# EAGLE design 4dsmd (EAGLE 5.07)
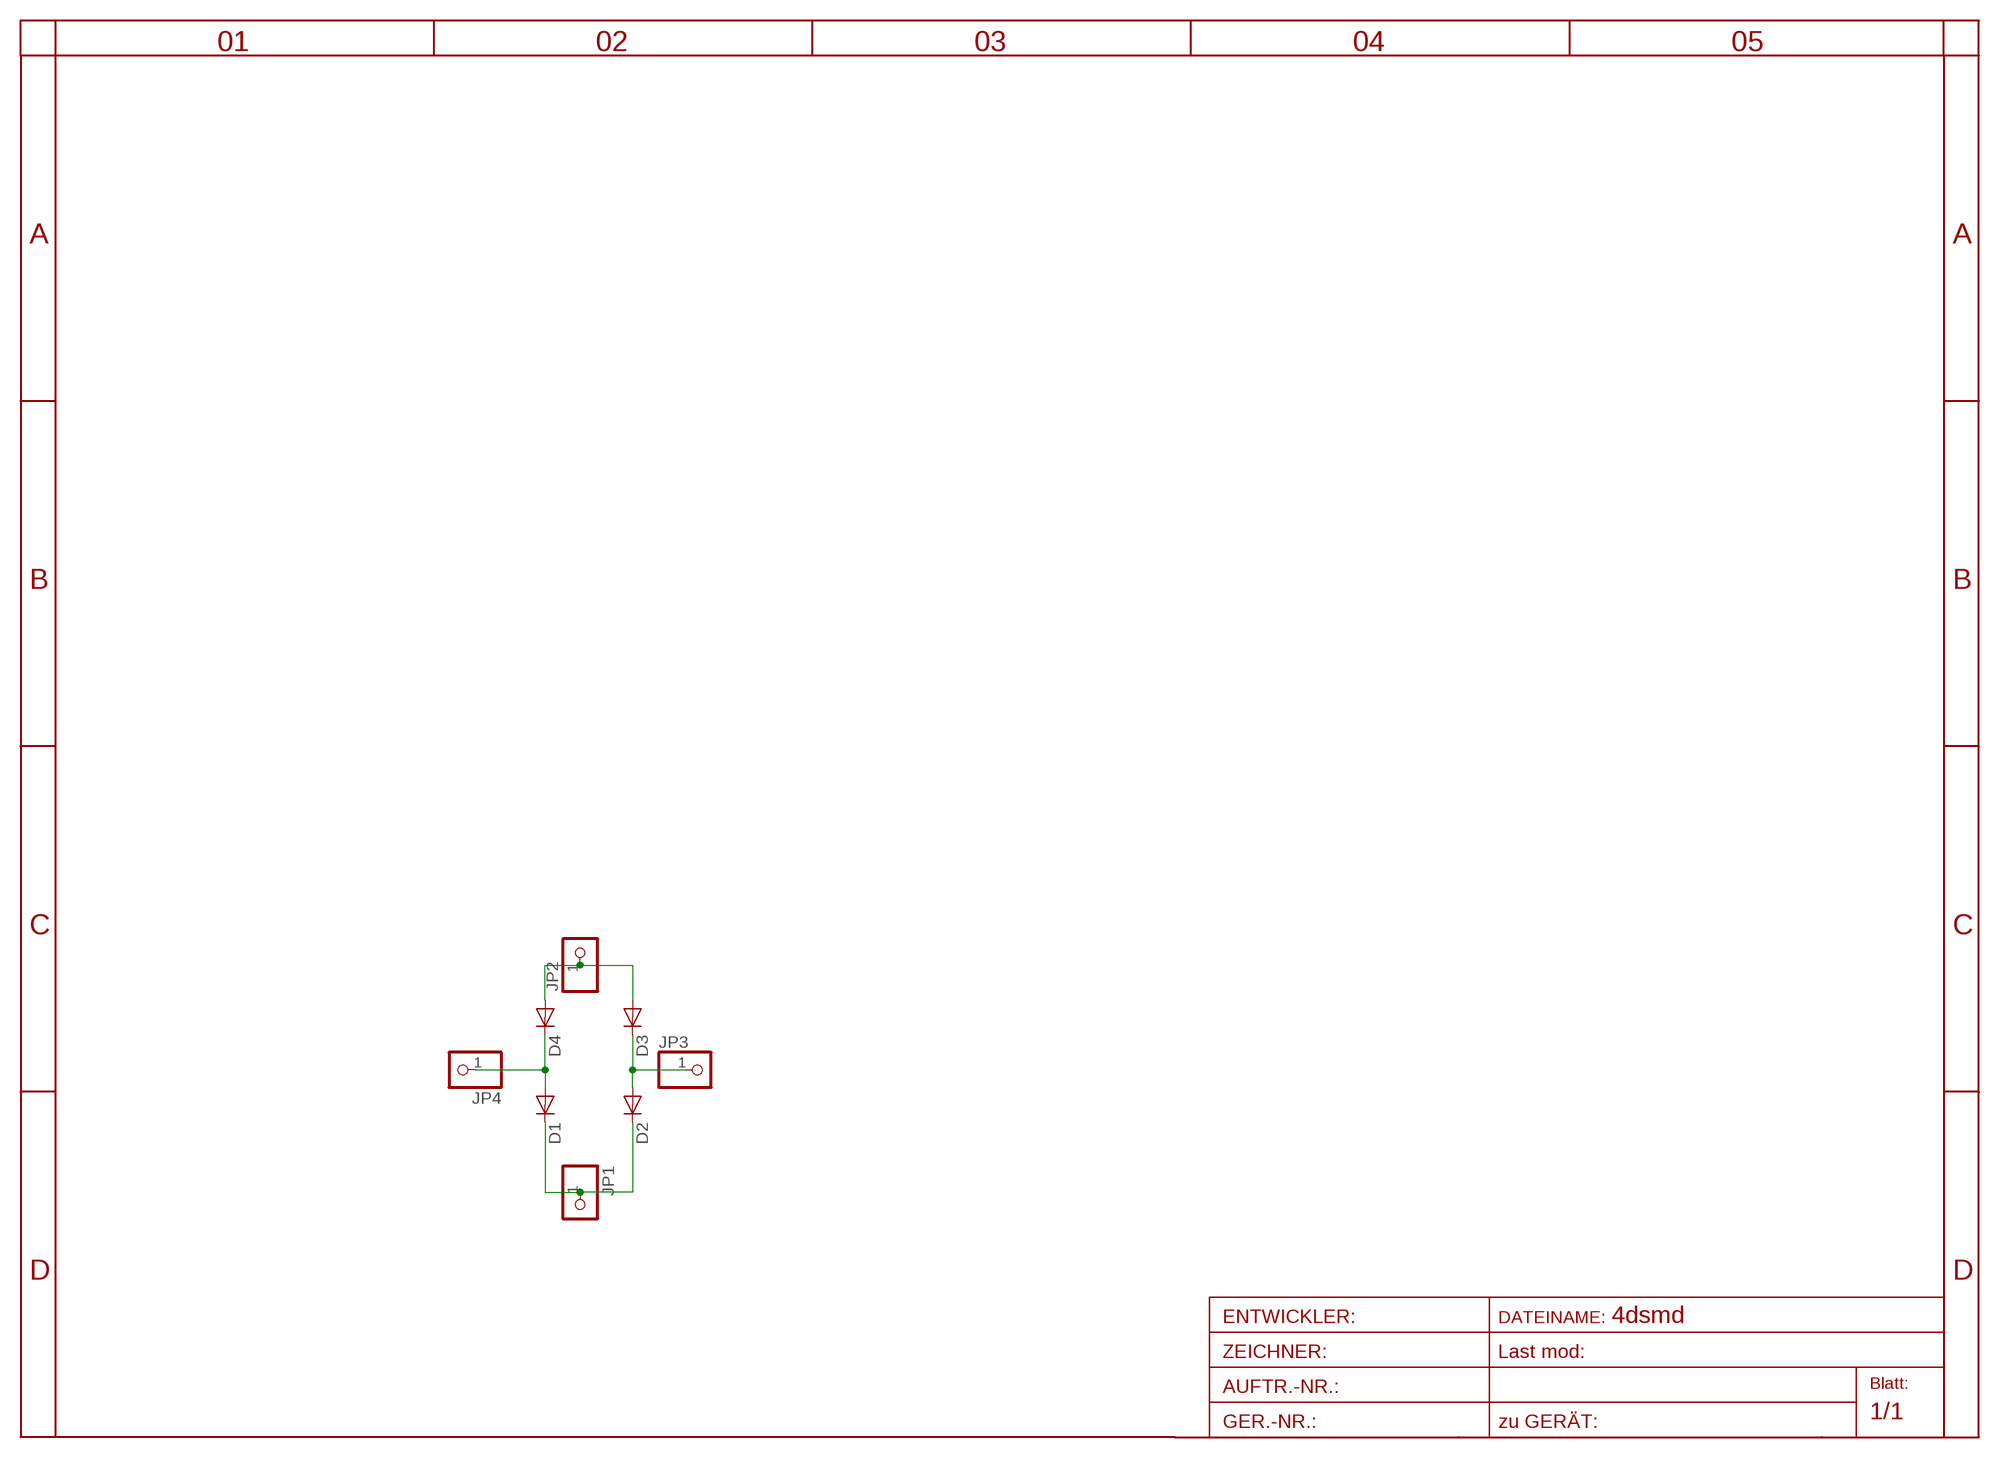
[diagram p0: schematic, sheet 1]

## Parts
D1  DIODE-SMC  [SMC]
D2  DIODE-SMC  [SMC]
D3  DIODE-SMC  [SMC]
D4  DIODE-SMC  [SMC]
JP1  PINHD-1X12MM2  [1X2MM2]
JP2  PINHD-1X12MM2  [1X2MM2]
JP3  PINHD-1X12MM2  [1X2MM2]
JP4  PINHD-1X12MM2  [1X2MM2]

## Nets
AC1: D1.A D4.C JP4.1
AC2: D2.A D3.C JP3.1
MINUS: D3.A D4.A JP2.1
PLUS: D1.C D2.C JP1.1

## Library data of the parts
D1-D4 = diode:DIODE-: DIODE
JP1-JP4 = pinhead:PINHD-1X1: PIN HEADER

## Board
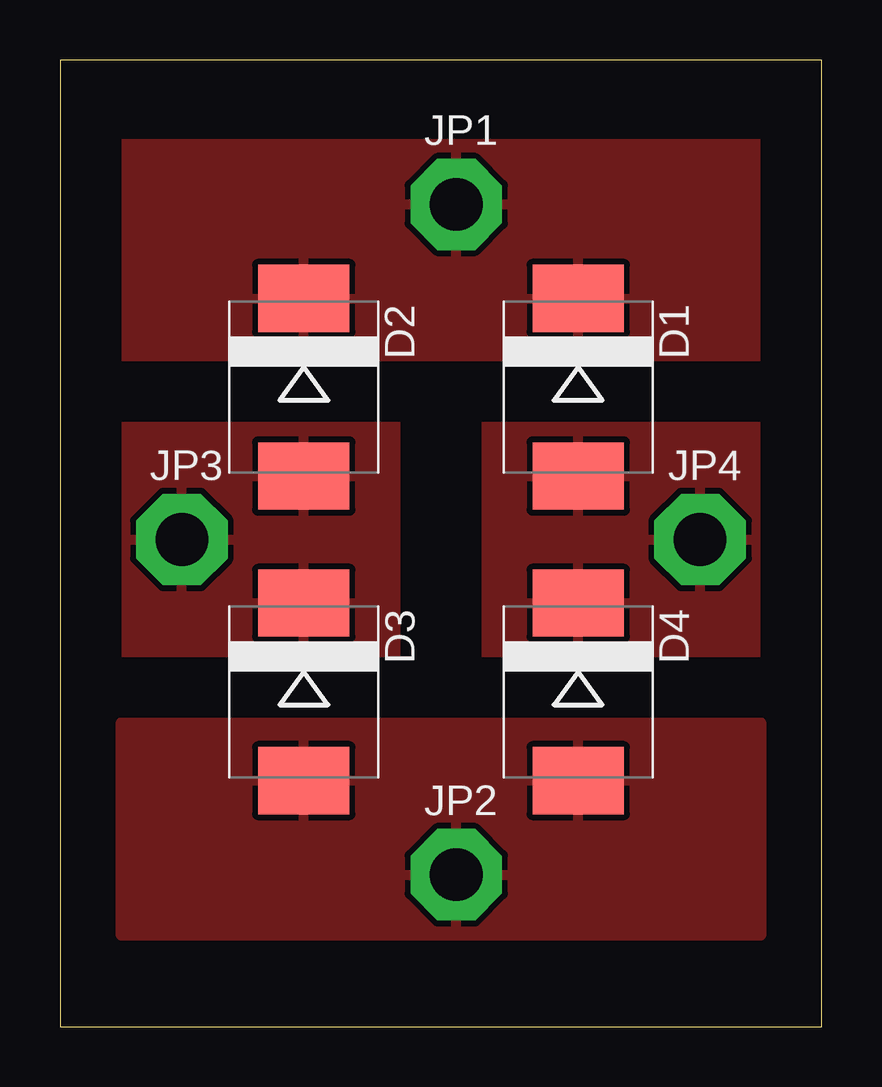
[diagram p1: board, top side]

Size 31.73 x 40.31 mm. Coordinates in mm from the lower left corner, seen from the top.
Outline: 0,0 31.73,0 31.73,40.31 0,40.31 0,0
Copper layers (1*16): Top 0.035mm / dielectric 1.5mm / Bottom 0.035mm
Design rules "default": minimum track width 10mil, minimum drill 20mil, track to track 8mil, track to pad 8mil, pad to pad 8mil, via to via 8mil, smd to smd 8mil, copper to edge 40mil, drill to drill 8mil, minimum pad ring 1mil, minimum via ring 8mil, stop-mask expansion 4mil, vias tented up to drill 0mil, thermal gap 10mil

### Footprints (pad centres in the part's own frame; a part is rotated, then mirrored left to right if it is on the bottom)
SMC = smd 2.8 x 3.8: A 3.7,0; C -3.7,0
1X2MM2 = drill 2.2 pad 3.81 octagon: 1 0,0

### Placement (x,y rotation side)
D1  21.59,26.67 270 top
D2  10.16,26.67 270 top
D3  10.16,13.97 270 top
D4  21.59,13.97 270 top
JP1  16.51,34.29 0 top
JP2  16.51,6.35 0 top
JP3  5.08,20.32 0 top
JP4  26.67,20.32 0 top

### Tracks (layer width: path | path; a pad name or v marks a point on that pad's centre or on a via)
AC1
  pour Top (isolate 2.54, rank 2): 17.78,15.24 17.78,25.4 29.21,25.4 29.21,15.24
AC2
  pour Top (isolate 2.54, rank 2): 2.54,25.4 13.97,25.4 13.97,15.24 2.54,15.24
MINUS
  pour Top: 2.54,12.7 29.21,12.7 29.21,3.81 2.54,3.81
PLUS
  pour Top (isolate 2.54): 2.54,36.83 29.21,36.83 29.21,27.94 2.54,27.94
